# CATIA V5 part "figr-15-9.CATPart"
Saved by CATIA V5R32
Part number: Part1
Bounding box of the stored display mesh (mm): x -50 to 50, y -32.5 to 33.5, z -52 to 1
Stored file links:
  D:\PROJECTS\Project 2022\CATIA V5 6R 2022\Resources\Part Files\c15_catia_v5_6r2022_prt\figr-15-9.CATPart
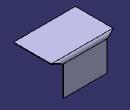
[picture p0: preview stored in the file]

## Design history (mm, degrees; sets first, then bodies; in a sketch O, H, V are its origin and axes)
SheetMetalParameters1: Thickness 1, BendRadius 4, KFactor 0.475772 {= log(min(100,max(20*SheetMetalParameters1.BendRadius,SheetMetalParameters1.Thickness)/SheetMetalParameters1.Thickness))/log(100)/2}, ReliefRadialLength 4, ReliefAxialLength 4, MinimumBendRadius 0
Body1 (main body)
  Sketch1 on xy-plane, origin (0, 0, 0), H (1, 0, 0), V (0, 1, 0)
    line L1 (-50, 32.5) -> (50, 32.5)
    line L2 (50, 32.5) -> (50, -32.5)
    line L3 (50, -32.5) -> (-50, -32.5)
    line L4 (-50, -32.5) -> (-50, 32.5)
    length L1 = 100
    length L2 = 65
    horizontal: L1 H, L3 H
    vertical: L2 V, L4 V
    symmetry: L4 L2 V, L1 L3 H
  Wall1: Thickness 1, Profile Sketch1
  d_NewWallOnEdge1: NewWallOnEdge_Edge edge [face of Wall1 | face of Wall1], NewWallOnEdge_Length 53, NewWallOnEdge_HeightLimitOffset 0, NewWallOnEdge_WidthOffset1 -15, NewWallOnEdge_WidthOffset2 -15, NewWallOnEdge_Angle 90, NewWallOnEdge_BendRadiusValue 4 {= SheetMetalParameters1.BendRadius}, NewWallOnEdge_BendTable SheetMetalParameters1, KFacteur 0.475772 {= log(min(100,max(20*d_NewWallOnEdge1.Radius,SheetMetalParameters1.Thickness)/SheetMetalParameters1.Thickness))/log(100)/2}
